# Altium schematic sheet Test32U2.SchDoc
size A4
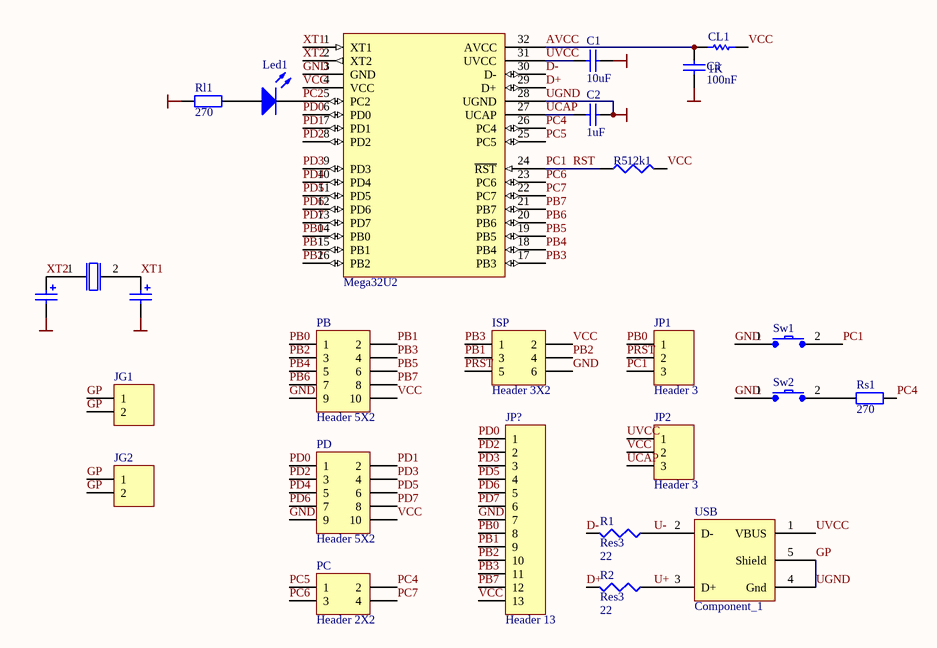
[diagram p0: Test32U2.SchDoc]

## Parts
?  Mega32U2  [ATMega32U2]
C1  value 10uF  [CC3216-1206]
C2  value 1uF  [CC3216-1206]
C3  value 100nF  [CC1608-0603]
CL1  value 1K  [AXIAL-0.3]  (hidden comment: Res1)
Cx1  Cap Pol3  [CC2012-0805]  (value not drawn)
Cx2  Cap Pol3  [CC2012-0805]  (value not drawn)
ISP  Header 3X2  [HDR2X3]
JG1  Header 2  [HDR1X2]  (value not drawn)
JG2  Header 2  [HDR1X2]  (value not drawn)
JP1  Header 3  [HDR1X3]
JP2  Header 3  [HDR1X3]
JP?  Header 13  [HDR1X13]
Led1  (no value)  [CC1608-0603]
PB  Header 5X2  [HDR2X5]
PC  Header 2X2  [HDR2X2]
PD  Header 5X2  [HDR2X5]
R1  Res3  value 22  [C1608-0603]
R2  Res3  value 22  [C1608-0603]
R5  value 12k1  [C1608-0603]
Rl1  value 270  [CR2012-0805]  (hidden comment: Res Semi)
Rs1  value 270  [CR2012-0805]  (hidden comment: Res Semi)
Sw1  Component_1  [MTS-1132]  (value not drawn)
Sw2  Component_1  [MTS-1132]  (value not drawn)
USB  Component_1  [USBB]
Xc1  Component_1  [HC49]  (value not drawn)

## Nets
GND: ?.3(GND) ?.28(UGND) C1.2 C2.2 C3.1 Cx1.2 Cx2.2 ISP.6 JG1.1 JG1.2 JG2.1 JG2.2 JP?.7 PB.9 PD.9 Sw1.1 Sw2.1 USB.4(Gnd) USB.5(Shield)  [also labelled GP, UGND]
VCC: ?.4(VCC) CL1.2 ISP.2 JP2.2 JP?.13 PB.10 PD.10 R5.2 Rl1.2
AVCC: ?.32(AVCC) C3.2 CL1.1
D+: ?.29(D+) R2.2
D-: ?.30(D-) R1.2
PB0: ?.14(PB0) JP1.1 JP?.8 PB.1
PB1: ?.15(PB1) ISP.3 JP?.9 PB.2
PB2: ?.16(PB2) ISP.4 JP?.10 PB.3
PB3: ?.17(PB3) ISP.1 JP?.11 PB.4
PB4: ?.18(PB4) PB.5
PB5: ?.19(PB5) PB.6
PB6: ?.20(PB6) PB.7
PB7: ?.21(PB7) JP?.12 PB.8
PC1: ?.24(~{RST}) JP1.3 R5.1 Sw1.2  [also labelled RST]
PC2: ?.5(PC2) Led1.2(K)
PC4: ?.26(PC4) PC.2 Rs1.1
PC5: ?.25(PC5) PC.1
PC6: ?.23(PC6) PC.3
PC7: ?.22(PC7) PC.4
PD0: ?.6(PD0) JP?.1 PD.1
PD1: ?.7(PD1) PD.2
PD2: ?.8(PD2) JP?.2 PD.3
PD3: ?.9(PD3) JP?.3 PD.4
PD4: ?.10(PD4) PD.5
PD5: ?.11(PD5) JP?.4 PD.6
PD6: ?.12(PD6) JP?.5 PD.7
PD7: ?.13(PD7) JP?.6 PD.8
PRST: ISP.5 JP1.2
U+: R2.1 USB.3(D+)
U-: R1.1 USB.2(D-)
UCAP: ?.27(UCAP) C2.1 JP2.3
UVCC: ?.31(UVCC) C1.1 JP2.1 USB.1(VBUS)
XT1: ?.1(XT1) Cx1.1 Xc1.2
XT2: ?.2(XT2) Cx2.1 Xc1.1
NetLed1_1: Led1.1(A) Rl1.1
NetRs1_2: Rs1.2 Sw2.2

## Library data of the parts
? = Component_1
C1-C3 = Cap Semi: Capacitor (Semiconductor SIM Model)
CL1 = Res1: Resistor
Cx1 Cx2 = Cap Pol3: Polarized Capacitor (Surface Mount); Value: 18pF
ISP = Header 3X2: Header, 3-Pin, Dual row
JG1 JG2 = Header 2: Header, 2-Pin
JP1 JP2 = Header 3: Header, 3-Pin
JP? = Header 13: Header, 13-Pin
Led1 = LED3: Typical BLUE SiC LED; Revision 1: Jul-2002: Re-released for DXP Platform.; Revision 2: 17-Dec-2003: PCB Footprint replaced.
PB PD = Header 5X2: Header, 5-Pin, Dual row
PC = Header 2X2: Header, 2-Pin, Dual row
R1 R2 R5 = Res3: Resistor
Rl1 Rs1 = Res Semi: Semiconductor Resistor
